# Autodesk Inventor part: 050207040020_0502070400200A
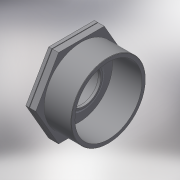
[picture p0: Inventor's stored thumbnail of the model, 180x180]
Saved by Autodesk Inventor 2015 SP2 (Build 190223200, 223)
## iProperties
Created: 2017-05
Part Number: 050207040020_0502070400200A
Material: Generic
Description: PLASSON REDUCING BUSHING 4"-2"
Document SubType Name: Modeling
Designer: KIM
Density: 1 g/cm^3
Appearance: Default
Author: KIM
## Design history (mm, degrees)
derived "050207.ipt"
feature "Solid1::050207.ipt"
tag "TaggingFeature1"
body "Solid1"
other parameters: "d1" = 113.03, "d5" = 41, "d8" = 0.56, "d12" = 0, "d15" = 56, "d19" = 0, "d30" = 9.33333, "d31" = 4.66667, "d33" = 56.656, "d34" = 101.727, "d36" = 6, "d37" = 67.9872, "d38" = 44.8, "d39" = 50.9904, "d40" = 4.1, "d41" = 0, "H_" = 56, "R_" = 113.03, "l_2" = 41, "Rp_" = 56.656
